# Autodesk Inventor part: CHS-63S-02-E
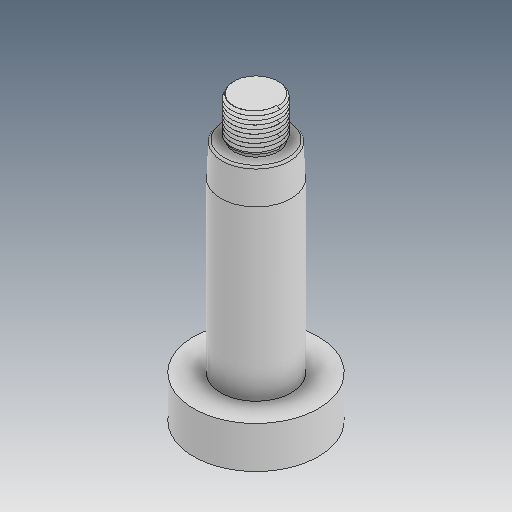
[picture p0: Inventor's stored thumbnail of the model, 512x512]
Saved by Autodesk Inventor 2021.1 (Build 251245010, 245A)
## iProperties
Created: 2019-05
Part Number: CHS-63S-02-E
Material: Ogólny
Document SubType Name: Modeling
Designer: user
Density: 1 g/cm^3
Appearance: Domyślna
Author: user
Revision Number: ÈÎºÎ
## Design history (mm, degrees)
feature "ÊäÈë1"
feature "ÊäÈë2"
node "Bryła1"
node "Bryła2"
